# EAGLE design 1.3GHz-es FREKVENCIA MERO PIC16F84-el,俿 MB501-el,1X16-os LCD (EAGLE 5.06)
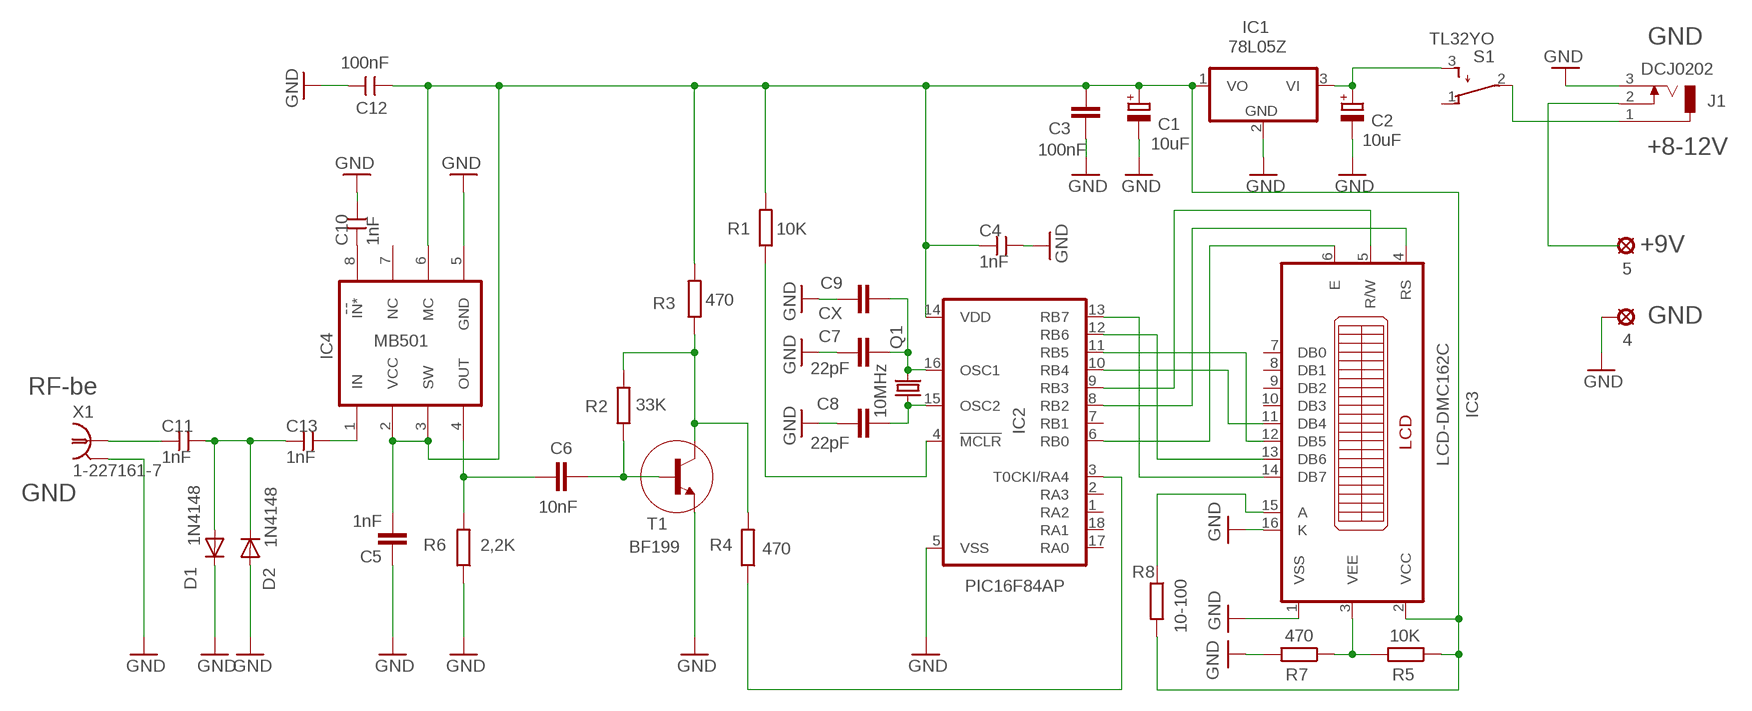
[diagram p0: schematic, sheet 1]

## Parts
4  BE  LSP10  [LSP10]
5  BE  LSP10  [LSP10]
C1  10uF  CPOL-EUE2,5-6E  [E2,5-6E]
C2  10uF  CPOL-EUE2,5-6E  [E2,5-6E]
C3  100nF  C-EU025-024X044  [C025-024X044]
C4  1nF  CAP-0805  [0805]
C5  1nF  C-EU025-024X044  [C025-024X044]
C6  10nF  C-EU025-024X044  [C025-024X044]
C7  22pF  C-EU025-024X044  [C025-024X044]
C8  22pF  C-EU025-024X044  [C025-024X044]
C9  CX  C-EU025-024X044  [C025-024X044]
C10  1nF  CAP-0805  [0805]
C11  1nF  CAP-0805  [0805]
C12  100nF  CAP-0805  [0805]
C13  1nF  CAP-0805  [0805]
D1  1N4148  DIODE-MINIMELF  [MINIMELF]
D2  1N4148  DIODE-MINIMELF  [MINIMELF]
IC1  78L05Z  [TO92]
IC2  PIC16F84AP  [DIL18]
IC3  LCD-DMC162C  [DMC-162C]
IC4  MB501MB501  [DIL08]
J1  DCJ0202  [DCJ0202]
Q1  10MHz  CRYSTALHC49S  [HC49/S]
R1  10K  R-EU_0204/7  [0204/7]
R2  33K  R-EU_0204/7  [0204/7]
R3  470  R-EU_0204/7  [0204/7]
R4  470  R-EU_0204/7  [0204/7]
R5  10K  R-EU_0204/7  [0204/7]
R6  2,2K  R-EU_0204/7  [0204/7]
R7  470  R-EU_0204/7  [0204/7]
R8  10-100  R-EU_0204/7  [0204/7]
S1  TL32YO  [TL3XYO]
T1  BF199  [TO92]
X1  1-227161-7  [AMP_227161]

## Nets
GND: 4.MP C1.- C2.- C3.2 C4.P$2 C5.1 C7.1 C8.1 C9.1 C10.P$2 C12.P$2 D1.C D2.A IC1.2(GND) IC2.5(VSS) IC3.1(VSS) IC3.16(K) IC4.5(GND) J1.3 R6.1 R7.2 T1.2(E) X1.2(GND)
N$1: IC2.6(RB0) IC3.6(E)
N$2: IC2.8(RB2) IC3.4(RS)
N$3: IC2.9(RB3) IC3.5(R/W)
N$4: IC2.10(RB4) IC3.11(DB4)
N$5: IC2.11(RB5) IC3.12(DB5)
N$6: IC2.12(RB6) IC3.13(DB6)
N$7: IC2.13(RB7) IC3.14(DB7)
N$8: C1.+ C3.1 C4.P$1 C5.2 C12.P$1 IC1.1(VO) IC2.14(VDD) IC3.2(VCC) IC4.2(VCC) IC4.3(SW) IC4.6(MC) R1.2 R3.2 R5.1 R8.2
N$9: C2.+ IC1.3(VI) S1.3(S)
N$10: R2.2 R3.1 R4.2 T1.3(C)
N$11: C7.2 C9.2 IC2.16(OSC1) Q1.2
N$12: C8.2 IC2.15(OSC2) Q1.1
N$13: IC2.4(!MCLR) R1.1
N$14: C6.1 IC4.4(OUT) R6.2
N$15: IC3.3(VEE) R5.2 R7.1
N$16: IC2.3(T0CKI/RA4) R4.1
N$17: C6.2 R2.1 T1.1(B)
N$18: C11.P$2 C13.P$1 D1.A D2.C
N$19: J1.1 S1.2(P)
N$20: C10.P$1 IC4.8(IN*)
N$21: C13.P$2 IC4.1(IN)
N$22: IC3.15(A) R8.1
N$23: C11.P$1 X1.1
N$24: 5.MP J1.2
Unconnected: IC2.1(RA2) IC2.2(RA3) IC2.7(RB1) IC2.17(RA0) IC2.18(RA1) IC3.7(DB0) IC3.8(DB1) IC3.9(DB2) IC3.10(DB3) IC4.7(NC) S1.1(O)

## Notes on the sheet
- GND
- +8-12V
- +9V
- GND
- RF-be
- GND

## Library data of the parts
4 5 = solpad:LSP10: SOLDER PAD
C1 C2 = rcl:CPOL-EU: POLARIZED CAPACITOR, European symbol
C3 C5-C9 = rcl:C-EU: CAPACITOR, European symbol
C4 C10-C13 = scenix4:CAP-0805
D1 D2 = diode:DIODE-: DIODE
IC1 = Eigene:78*: Positive VOLTAGE REGULATOR Source: http://cache.national.com/ds/LM/LM78L05.pdf http://www.fairchildsemi.com/ds/LM/LM7805.pdf
IC2 = microchip:PIC16F8*: MICROCONTROLLER 8-Bit PIC16F8X Family - CMOS Flash/EEPROM Pin Compatible : PIC16F83, PIC16CR83, PIC16F84A, PIC16CR84 see also PIC16C*
IC3 = dodolcd:LCD-DMC162C: DISPLAY DMC 162C BACKLIGHT 16X2
IC4 = MB501:MB501: MB501-64/65,128/129 DIVIDER
J1 = con-jack:DCJ0202: DC POWER JACK Source: DCJ0202.pdf
Q1 = crystal:CRYSTAL: CRYSTAL
R1-R8 = rcl:R-EU_: RESISTOR, European symbol
S1 = switch:TL32YO: TINY SWITCH ON - MOM Source: http://www2.produktinfo.conrad.com/datenblaetter/700000-724999/705152-da-01-de-Subminiaturschalter_TL_36YO.pdf
T1 = transistor:BF199: NPN TRANSISTOR
X1 = con-coax:?227161*: JACK, RIGHT ANGLE, 50 OHM, PCB, BNC

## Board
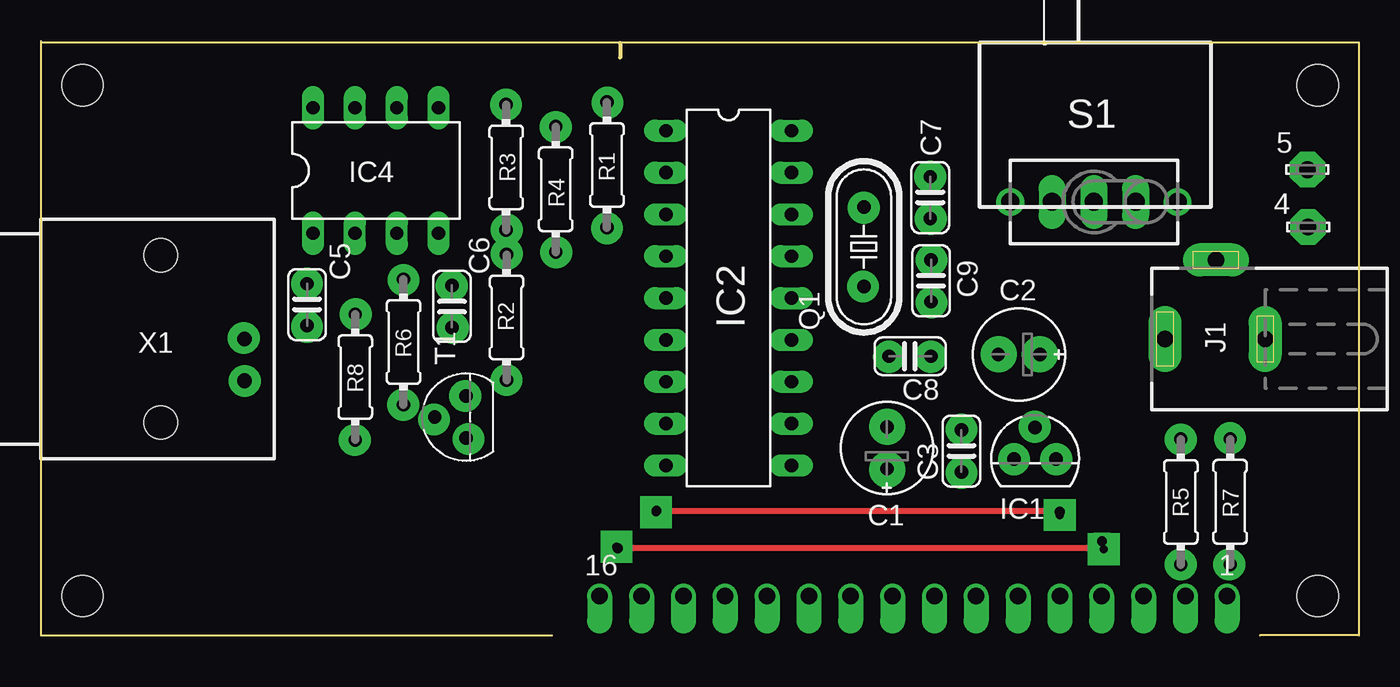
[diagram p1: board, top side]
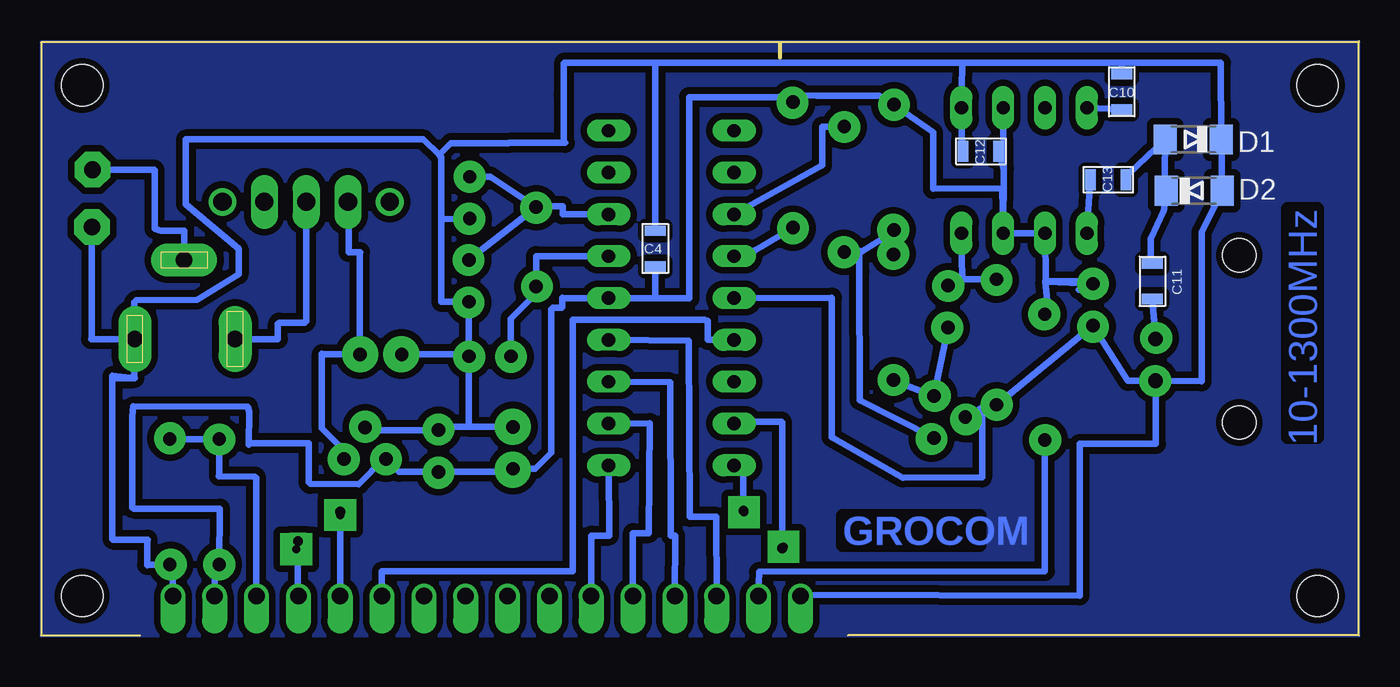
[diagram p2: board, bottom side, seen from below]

Size 80 x 36.08 mm. Coordinates in mm from the lower left corner, seen from the top.
Outline: 0,36 0,36.08 0,0
Outline: 0,36 0,0
Outline: 0,36 80,36 80,0 74,0
Outline: 35.15,35.97 35.15,35.08
Outline: 0,0 31,0
Copper layers (1*16): Top 0.035mm / dielectric 1.5mm / Bottom 0.035mm
Design rules "default *": minimum track width 10mil, minimum drill 24mil, track to track 8mil, track to pad 8mil, pad to pad 8mil, via to via 8mil, smd to smd 8mil, copper to edge 0mil, drill to drill 8mil, minimum pad ring 10mil, minimum via ring 8mil, stop-mask expansion 4mil, vias tented up to drill 0mil, thermal gap 10mil

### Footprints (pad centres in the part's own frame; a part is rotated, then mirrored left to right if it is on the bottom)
LSP10 = drill 1.016 pad 2.159 octagon: MP 0,0
E2,5-6E = drill 0.813 pad 1.575 round: + -1.27,0 | drill 0.813 pad 1.575 octagon: - 1.27,0
C025-024X044 = drill 0.813 octagon: 1 -1.27,0; 2 1.27,0
0805 = smd 0.635 x 1.27: P$1 1.143,0; P$2 -1.016,0
MINIMELF = smd 1.4 x 1.8: A 1.7,0; C -1.7,0
TO92 = drill 0.813 octagon: 1 -1.27,0; 2 0,1.905; 3 1.27,0
DIL18 = drill 0.813 long: 1 -10.16,-3.81; 2 -7.62,-3.81; 3 -5.08,-3.81; 4 -2.54,-3.81; 5 0,-3.81; 6 2.54,-3.81; 7 5.08,-3.81; 8 7.62,-3.81; 9 10.16,-3.81; 10 10.16,3.81; 11 7.62,3.81; 12 5.08,3.81; 13 2.54,3.81; 14 0,3.81; 15 -2.54,3.81; 16 -5.08,3.81; 17 -7.62,3.81; 18 -10.16,3.81
DMC-162C = drill 1 offset: 1 8,33.5; 2 10.54,33.5; 3 13.08,33.5; 4 15.62,33.5; 5 18.16,33.5; 6 20.7,33.5; 7 23.24,33.5; 8 25.78,33.5; 9 28.32,33.5; 10 30.86,33.5; 11 33.4,33.5; 12 35.94,33.5; 13 38.48,33.5; 14 41.02,33.5; 15 43.56,33.5; 16 46.1,33.5 | hole 2.5: 2.5,2.5; 77.5,2.5; 77.5,33.5; 2.5,33.5
DIL08 = drill 0.813 long: 1 -3.81,-3.81; 2 -1.27,-3.81; 3 1.27,-3.81; 4 3.81,-3.81; 5 3.81,3.81; 6 1.27,3.81; 7 -1.27,3.81; 8 -3.81,3.81
DCJ0202 = drill 1 pad 2 long: 1 0,3.1; 2 4.8,0; 3 0,-3
HC49/S = drill 0.813 round: 1 -2.413,0; 2 2.413,0
0204/7 = drill 0.813 octagon: 1 -3.81,0; 2 3.81,0
TL3XYO = drill 1.1 pad 1.422 long: 1 -2.54,0; 2 0,0; 3 2.54,0 | drill 1.1 pad 1.676 round: M1 -5.08,0; M2 5.08,0
TO92' = drill 0.813 octagon: 1 1.27,0; 2 0,1.905; 3 -1.27,0
AMP_227161 = drill 0.9 pad 1.27 round: 1 0,-5.08; 2 -2.54,-5.08 | hole 2: -5.08,0; 5.08,0

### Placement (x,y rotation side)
4  76.92,24.79 0 top
5  76.88,28.28 0 top
C1  51.34,11.39 90 top
C2  59.38,17.06 180 top
C3  55.87,11.19 90 top
C4  42.72,23.55 270 bottom
C5  16.14,20.08 90 top
C6  24.94,19.97 270 top
C7  53.98,26.58 90 top
C8  52.76,16.95 180 top
C9  54.03,21.53 90 top
C10  14.4,33.08 270 bottom
C11  12.53,21.56 270 bottom
C12  23.01,29.4 0 bottom
C13  15.28,27.67 0 bottom
D1  10.05,30.11 180 bottom
D2  10,27 0 bottom
IC1  60.34,10.72 0 top
IC2  41.74,20.48 270 top
IC3  80.01,35.89 180 top
IC4  20.32,28.23 0 top
J1  71.32,18 90 top
Q1  49.95,23.59 90 top
R1  34.35,28.57 90 top
R2  28.25,19.31 90 top
R3  28.23,28.42 90 top
R4  31.24,27.09 270 top
R5  69.19,8.1 90 top
R6  22,17.82 90 top
R7  72.19,8.11 270 top
R8  19.07,15.69 90 top
S1  63.91,26.32 180 top
T1  BF199  [TO92']  25.8,13.26 90 top
X1  7.26,18 90 top

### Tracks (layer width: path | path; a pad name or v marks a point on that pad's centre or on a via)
GND
  Bottom 0.406: X1.2 9.54,15.42 9.54,24.48 D2.A D1.C 8.37,34.77 14.39,34.77 | 14.39,34.77 24.07,34.77 24.07,34.58 | 24.07,34.58 IC4.5 24.12,30.23 C12.P$2 | 14.39,34.77 C10.P$2 | X1.2 14.02,15.45 C5.1 R6.1 T1.2 22.88,13.86 22.88,9.59 27.7,9.58 32.01,12.04 32.01,19.92 32,20.5 IC2.5 | IC3.16 33.99,2.47 16.95,2.42 16.95,11.62 12.32,11.62 X1.2 | 55.7,25.27 C7.1 | 55.7,25.27 55.7,20.25 C9.1 C8.1 | 42.76,34.78 24.17,34.77 24.07,34.58 | 55.7,25.27 55.7,29.03 55.84,29.17 | C8.1 54.13,17.06 C2.- | C4.P$2 42.72,24.6 42.72,24.61 42.72,34.73 42.76,34.78 | 54,12.66 C1.- | 54,12.66 55.68,12.66 C3.2 60.19,12.46 IC1.2 | C8.1 54.03,12.68 54,12.66 | IC3.1 72.01,3.95 R7.2 73.54,4.3 73.57,4.27 73.57,5.78 73.54,5.81 75.65,5.81 75.68,5.84 75.68,15.75 | 75.68,15.75 75.63,15.61 74.38,15.61 74.36,15.68 J1.3 74.33,17.98 76.97,17.98 76.92,18.04 4.MP | 42.76,34.78 48.23,34.78 48.27,34.73 48.27,32.82 48.27,32.81 48.27,29.94 48.19,29.9 51.59,29.9 51.64,29.88 55.13,29.88 55.84,29.17 | 75.68,15.75 74.33,15.62 74.35,15.68 74.35,20.22 74.23,20.34 70.53,20.39 68.01,21.91 68.01,23.47 71.21,26.19 71.21,30.12 56.79,30.12 55.84,29.17
N$1
  Bottom 0.406: IC2.6 39.53,17.94 39.53,19.12 39.76,19.16 39.71,19.16 47.72,19.16 47.72,3.89 59.31,3.89 IC3.6
N$2  (via drill 0.6)
  Top 0.406: v35.01,5.28 64.36,5.31 v64.41,5.71
  Bottom 0.406: IC2.8 37.92,12.97 37.91,12.98 35.06,12.98 35.01,12.93 v35.01,5.28 | v64.41,5.71 64.41,2.41 IC3.4
N$3  (via drill 0.6)
  Top 0.406: v37.36,7.58 61.8,7.55 v61.85,7.5
  Bottom 0.406: IC2.9 37.46,10.32 37.36,10.28 v37.36,7.58 | v61.85,7.5 IC3.5
N$4
  Bottom 0.406: IC2.10 45.51,6.06 46.59,6.06 IC3.11
N$5
  Bottom 0.406: IC2.11 43.05,12.9 43.1,6.22 44.07,6.22 IC3.12
N$6
  Bottom 0.406: IC2.12 41.82,15.36 41.77,6.06 41.51,6.06 IC3.13
N$7
  Bottom 0.406: IC2.13 40.67,17.9 40.62,7.2 39.03,7.2 IC3.14
N$8
  Bottom 0.406: IC4.3 IC4.2 19.01,21.46 C5.2 17,21 16.21,21.51 19.03,21.51 18.89,20.02 R8.2 | IC4.3 21.55,28.34 | 21.55,28.34 IC4.6 | 21.55,28.34 C12.P$1 | IC4.3 21.64,27.15 25.84,27.12 25.84,30.54 R3.2 29.1,32.76 32.87,32.75 34.16,32.81 R1.2 34.46,32.67 40.66,32.68 40.65,20.46 42.77,20.47 | 42.77,20.47 IC2.14 48.35,20.48 48.35,20.49 48.35,19.95 48.4,19.91 48.94,19.91 49.03,19.81 49.03,11.09 50.01,10.12 C1.+ 51.53,9.92 C3.1 58.28,9.92 IC1.1 59.2,10.71 60.71,9.17 63.68,9.2 63.76,9.29 63.76,11.67 67.31,11.67 67.4,11.59 67.36,13.57 67.45,13.89 74.42,13.91 74.46,13.32 74.46,7.74 74.37,7.7 69.15,7.7 R5.1 69.47,4.02 IC3.2 | C4.P$1 42.72,20.52 42.77,20.47
N$9
  Bottom 0.406: IC1.3 61.96,11.06 61.96,11.59 62.95,12.58 62.95,17.09 62.92,17.06 C2.+ 60.65,23.26 60.64,23.27 61.33,23.27 61.33,26.28 S1.3
N$10
  Bottom 0.406: R3.1 R2.2 28.46,24.39 30.16,23.33 R4.2 30.33,23.36 30.33,22.1 30.3,14.28 T1.3
N$11
  Bottom 0.406: IC2.16 48.34,25.56 48.34,26.06 49.95,26.06 Q1.2 | Q1.2 52.73,27.86 C7.2 | Q1.2 C9.2
N$12
  Bottom 0.406: IC2.15 49.95,23.02 Q1.1 49.95,20.78 51.5,19.23 51.5,16.96 C8.2
N$13
  Bottom 0.406: R1.1 36.65,23.37 IC2.4
N$14
  Bottom 0.406: R6.2 24.07,21.63 | 24.07,21.63 IC4.4 | 24.07,21.63 C6.1
N$15
  Bottom 0.406: R7.1 R5.2 69.19,11.8 69.2,11.79 69.2,9.78 69.21,9.68 67.02,9.65 66.95,9.58 66.95,2.41 IC3.3
N$16
  Bottom 0.406: IC2.3 32.59,28.53 32.58,30.89 R4.1
N$17
  Bottom 0.406: C6.2 T1.1 R2.1
N$18
  Bottom 0.406: C11.P$2 12.64,22.5 12.64,24.07 11.83,25.79 11.83,25.93 | 11.83,25.93 D1.A 14,28 14.11,27.79 C13.P$1 | 11.83,25.93 D2.C
N$19
  Bottom 0.406: S1.2 63.91,19.07 63.99,19 65.56,19 65.64,18.92 65.64,17.98 68.2,17.98 J1.1
N$20
  Bottom 0.406: C10.P$1 IC4.8
N$21
  Bottom 0.406: IC4.1 C13.P$2
N$22
  Bottom 0.406: R8.1 19.06,3.9 36.41,3.86 IC3.15
N$23
  Bottom 0.406: X1.1 C11.P$1
N$24
  Bottom 0.406: 5.MP 73.15,28.28 73.12,28.25 73.12,24.69 72.74,24.58 71.32,24.58 J1.2
N$25  (via drill 0.5 pad 2.18)
  other vias: 51.35,10.07
N$26  (via drill 0.5 pad 2.18)
  other vias: 51.35,12.67
N$27  (via drill 0.5 pad 2.18)
  other vias: 58.13,17.08
N$28  (via drill 0.5 pad 2.18)
  other vias: 60.64,17.08
N$29  (via drill 0.5 pad 1.93)
  other vias: 59.07,10.7
N$30  (via drill 0.5 pad 1.93)
  other vias: 60.32,12.67
N$31  (via drill 0.5 pad 1.93)
  other vias: 61.62,10.7
N$32  (via drill 0.5 pad 1.93)
  other vias: 51.47,16.92
N$33  (via drill 0.5 pad 1.93)
  other vias: 54.01,16.92
N$34  (via drill 0.5 pad 1.93)
  other vias: 55.88,12.5
N$35  (via drill 0.5 pad 1.93)
  other vias: 55.88,9.88
N$36  (via drill 0.5 pad 1.93)
  other vias: 69.19,11.9
N$37  (via drill 0.5 pad 1.93)
  other vias: 72.18,11.98
N$38  (via drill 0.5 pad 1.93)
  other vias: 69.19,4.3
N$39  (via drill 0.5 pad 1.93)
  other vias: 72.14,4.3
N$40  (via drill 0.5 pad 1.93)
  other vias: 53.97,27.84
N$41  (via drill 0.5 pad 1.93)
  other vias: 54.01,25.3
N$42  (via drill 0.5 pad 1.93)
  other vias: 54.05,22.79
N$43  (via drill 0.5 pad 1.93)
  other vias: 54.05,20.21
N$44  (via drill 0.5 pad 1.93)
  other vias: 49.9,21.18
N$45  (via drill 0.5 pad 1.93)
  other vias: 49.94,25.97
N$46  (via drill 0.5 pad 1.93)
  other vias: 34.39,32.33
N$47  (via drill 0.5 pad 1.93)
  other vias: 31.25,30.87
N$48  (via drill 0.5 pad 1.93)
  other vias: 28.22,32.22
N$49  (via drill 0.5 pad 1.93)
  other vias: 28.26,24.62
N$50  (via drill 0.5 pad 1.93)
  other vias: 28.26,23.16
N$51  (via drill 0.5 pad 1.93)
  other vias: 31.27,23.26
N$52  (via drill 0.5 pad 1.93)
  other vias: 34.36,24.72
N$53  (via drill 0.5 pad 1.93)
  other vias: 22,21.58
N$54  (via drill 0.5 pad 1.93)
  other vias: 24.94,21.22
N$55  (via drill 0.5 pad 1.93)
  other vias: 24.99,18.67
N$56  (via drill 0.5 pad 1.93)
  other vias: 28.26,15.5
N$57  (via drill 0.5 pad 1.93)
  other vias: 25.74,14.54
N$58  (via drill 0.5 pad 1.93)
  other vias: 23.85,13.11
N$59  (via drill 0.5 pad 1.93)
  other vias: 25.95,11.92
N$60  (via drill 0.5 pad 1.93)
  other vias: 21.98,14
N$61  (via drill 0.5 pad 1.93)
  other vias: 19.05,11.87
N$62  (via drill 0.5 pad 1.93)
  other vias: 19.1,19.5
N$63  (via drill 0.5 pad 1.93)
  other vias: 16.14,18.75
N$64  (via drill 0.5 pad 1.93)
  other vias: 16.14,21.35
N$65  (via drill 0.5 pad 1.93)
  other vias: 12.3,18.05
N$66  (via drill 0.5 pad 1.93)
  other vias: 12.36,15.45
N$67  (via drill 0.5 pad 1.93)
  other vias: 61.84,7.3
N$68  (via drill 0.5 pad 1.93)
  other vias: 64.51,5.23
N$69  (via drill 0.5 pad 1.93)
  other vias: 37.33,7.49
N$70  (via drill 0.5 pad 1.93)
  other vias: 34.93,5.38
N$71  (via drill 0.5 pad 1.93)
  other vias: 2.51,33.4
N$72  (via drill 0.5 pad 1.93)
  other vias: 2.54,2.39
N$73  (via drill 0.5 pad 1.93)
  other vias: 77.52,2.36
N$74  (via drill 0.5 pad 1.93)
  other vias: 77.56,33.41
N$75  (via drill 0.5 pad 1.93)
  other vias: 7.29,12.93
N$76  (via drill 0.5 pad 1.93)
  other vias: 7.23,23.09
N$77
  pour Bottom (isolate 0.406): 0,36 80,36 80,0 0,0

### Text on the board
Bottom: 10-1300MHz | GROCOM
